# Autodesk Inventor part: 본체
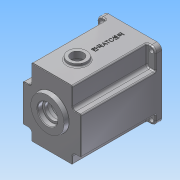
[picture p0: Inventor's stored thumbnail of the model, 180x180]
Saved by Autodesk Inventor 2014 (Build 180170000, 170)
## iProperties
Created: 2016-02
Part Number: 본체
Material: 알루미늄 6061
Document SubType Name: Modeling
Designer: mduedu
Density: 2.71 g/cm^3
Appearance: 알루미늄 - 평지
Mass: 1343.57 g
Surface Area: 1127.09 cm^2
Volume: 495.782 cm^3
Author: mduedu
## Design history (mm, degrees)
sketch "스케치1"
  geometry: L1 (-47, -47)-(47, -47); L2 (47, -47)-(47, 63); L3 (47, 63)-(-47, 63); L4 (-47, 63)-(-47, -47); 2 further points
  constraints: 8 end point, 2 parallel, 1 horizontal, 1 midpoint, 1 perpendicular, 1 vertical alignment
  dimensions: "d0" = 94 distance of L2.end L3.end; "d155" = 110 distance of L1.end L2.end; "d156" = 47 distance from line of L1 point (0, 0)
extrude "돌출1" new body sketch "스케치1" distance "d2" = 130; taper "d3" = 0 deg
sketch "스케치3"
  geometry: C1 r 40 at (0, 0); 1 further point
  constraints: 1 centre point, 1 coincident
  dimensions: "d9" = 80 diameter of C1
extrude "돌출3" cut sketch "스케치3" distance "d11" = 121; taper "d12" = 0 deg
sketch "스케치4"
  geometry: C1 r 21 at (0, 11); 1 further point
  constraints: 1 centre point, 1 vertical alignment
  dimensions: "d13" = 21 radius of C1; "d15" = 11 distance of point (0, 0) C1.centre
extrude "돌출4" join sketch "스케치4" distance "d16" = 7; taper "d17" = 0 deg
sketch "스케치5"
  geometry: C1 r 15 at (0, -20); 1 further point
  constraints: 1 centre point, 1 vertical alignment
  dimensions: "d18" = 15 radius of C1; "d20" = 20 distance of point (0, 0) C1.centre
extrude "돌출5" join sketch "스케치5" distance "d21" = 7; taper "d22" = 0 deg
sketch "스케치6"
  geometry: C1 r 28 at (0, 11); A1 r 21 centre (0, 11) between (8.978, -7.984) and (-8.978, -7.984) reference; 1 further point
  constraints: 1 centre point, 1 coincident
  dimensions: "d23" = 56 diameter of C1
extrude "돌출6" join sketch "스케치6" distance "d25" = 7; taper "d26" = -10 deg
hole "구멍1" diameter "d29" = 35; stored, may be unused: countersink angle "d33" = 90 deg, drill point angle "d35" = 0 deg; dims "d27" = 10, "d28" = 10, "d30" = 6, "d31" = 4, "d32" = 2, "d34" = 10
hole "구멍2" diameter "d38" = 22; stored, may be unused: countersink angle "d42" = 90 deg, drill point angle "d44" = 0 deg; dims "d36" = 10, "d37" = 10, "d39" = 6, "d40" = 4, "d41" = 2, "d43" = 7
hole "구멍3" diameter "d47" = 19; stored, may be unused: countersink angle "d51" = 90 deg, drill point angle "d53" = 0 deg; dims "d45" = 10, "d46" = 10, "d48" = 6, "d49" = 4, "d50" = 2, "d52" = 1
hole "구멍4" diameter "d56" = 32; stored, may be unused: countersink angle "d60" = 90 deg, drill point angle "d62" = 0 deg; dims "d54" = 10, "d55" = 10, "d57" = 6, "d58" = 4, "d59" = 2, "d61" = 8
hole "구멍5" diameter "d65" = 25; stored, may be unused: countersink angle "d69" = 90 deg, drill point angle "d71" = 0 deg; dims "d63" = 10, "d64" = 10, "d66" = 6, "d67" = 4, "d68" = 2, "d70" = 8
fillet "모깎기2" dims "d73" = 0.3
fillet "모깎기3" dims "d74" = 2
chamfer "모따기1" distance "d75" = 1; stored, may be unused: second distance "d76" = 2, angle "d77" = 45 deg
fillet "모깎기4" dims "d78" = 3
sketch "스케치16"
  geometry: L1 (-23, 32.726)-(23, 32.726); L2 (23, 32.726)-(23, 53); L3 (23, 53)-(-23, 53); L4 (-23, 53)-(-23, 32.726); L5 (-47, 63)-(47, 63) reference; 3 further points
  constraints: 8 end point, 2 parallel, 1 horizontal, 1 midpoint, 1 perpendicular, 1 vertical alignment, 2 other
  dimensions: "d160" = 46 distance of L2.end L3.end; "d163" = 10 distance between parallel lines of L3 L5
extrude "돌출15" cut sketch "스케치16" stored distance "d164" = 10; taper "d165" = 0 deg
fillet "모깎기5" dims "d79" = 2
fillet "모깎기15" dims "d166" = 5
sketch "스케치7"
  geometry: L1 (-23, 48)-(-23, 35.228) reference; L2 (23, 35.228)-(23, 48) reference; L3 (18, 53)-(-18, 53) reference; L4 (47, 63)-(47, -47) reference; L5 (47, -47)-(-47, -47) reference; L6 (-47, -47)-(-47, 63) reference; L7 (-47, 63)-(47, 63) reference; L8 (-26, 48)-(-26, 35.228); L9 (26, 35.228)-(26, 48); L10 (18, 56)-(-18, 56); C1 r 43 at (0, 0); A1 r 5 centre (-18, 48) between (-18, 53) and (-23, 48) reference; A2 r 5 centre (-28, 35.228) between (-24.889, 31.314) and (-23, 35.228) reference; A3 r 40 centre (0, 0) between (-24.889, 31.314) and (24.889, 31.314) reference; A4 r 5 centre (28, 35.228) between (23, 35.228) and (24.889, 31.314) reference; A5 r 5 centre (18, 48) between (23, 48) and (18, 53) reference; A6 r 8 centre (-18, 48) between (-18, 56) and (-26, 48); A7 r 2 centre (-28, 35.228) between (-26.756, 33.662) and (-26, 35.228); A8 r 43 centre (0, 0) between (-26.756, 33.662) and (26.756, 33.662); A9 r 2 centre (28, 35.228) between (26, 35.228) and (26.756, 33.662); A10 r 8 centre (18, 48) between (26, 48) and (18, 56); 1 further point
  constraints: 10 point on circle, 6 centre point, 6 end point, 1 coincident, 7 other
  dimensions: "d80" = 86 diameter of C1; "d167" = 3 distance between parallel lines of L3 L10
extrude "돌출7" cut sketch "스케치7" distance "d83" = 9; taper "d84" = 0 deg
sketch "스케치8" dims "d168" = 36
  geometry: L1 (-36, 4)-(-39.799, 4); L2 (-36, -4)-(-39.799, -4); A1 r 4 centre (-36, 0) between (-36, 4) and (-36, -4); A2 r 40 centre (0, 0) between (-24.889, 31.314) and (24.889, 31.314) reference; A3 r 40 centre (0, 0) between (-39.799, 4) and (-39.799, -4); 2 further points
  constraints: 5 point on circle, 4 end point, 2 centre point, 2 coincident, 2 horizontal alignment, 2 tangent, 1 horizontal, 1 parallel, 2 other
  dimensions: "d169" = 4 radius of A1
extrude "돌출9" join sketch "스케치8" stored distance "d89" = 9; taper "d90" = 0 deg
fillet "모깎기6" dims "d91" = 3.5
sketch "스케치9"
  geometry: L1 (47, 63)-(-47, 63) reference; L2 (47, -47)-(47, 63) reference; L3 (47, 63)-(33, 63); L4 (33, 63)-(33, 30); L5 (33, 30)-(47, 30); L6 (47, 30)-(47, 63); 2 further points
  constraints: 8 end point, 2 parallel, 1 horizontal, 1 perpendicular
  dimensions: "d95" = 33 distance from line of L4 point (0, 0); "d96" = 30 distance from line of L5 point (0, 0)
extrude "돌출10" cut sketch "스케치9" distance "d97" = 120; taper "d98" = 0 deg
sketch "스케치11"
  geometry: L1 (-40, -40)-(40, -40); L2 (40, -40)-(40, 56); L3 (40, 56)-(-40, 56); L4 (-40, 56)-(-40, -40); L5 (-47, -47)-(47, -47) reference; L6 (47, 63)-(-47, 63) reference; L7 (-47, 63)-(-47, -47) reference; C1 r 3.5 at (-40, 56); C2 r 3.5 at (40, 56); C3 r 3.5 at (40, -40); C4 r 3.5 at (-40, -40); 1 further point
  constraints: 8 end point, 4 centre point, 4 coincident, 3 equal radius, 2 parallel, 1 horizontal, 1 perpendicular
  dimensions: "d109" = 80 distance of L2.end L3.end; "d112" = 7 diameter of C1; "d157" = 7 distance from line of L1.start L5; "d158" = 7 distance between parallel lines of L6 L3; "d159" = 7 distance from line of L7 L3.end
extrude "돌출12" cut sketch "스케치11" stored distance "d113" = 63; taper "d114" = 0 deg
fillet "모깎기7" dims "d115" = 8
fillet "모깎기8" dims "d116" = 5
fillet "모깎기11" dims "d119" = 2
fillet "모깎기12" dims "d120" = 2
fillet "모깎기13" dims "d121" = 2
sketch "스케치12"
  geometry: 3 further points
  constraints: 2 horizontal alignment
hole "구멍6" sketch "스케치12" at (36, 0), (-36, 0) diameter "d122" = 3.242; stored, may be unused: countersink angle "d126" = 90 deg, drill point angle "d128" = 120 deg; dims "d123" = 7, "d124" = 4, "d125" = 2, "d127" = 9
sketch "스케치13"
  geometry: L1 (-33, 35)-(-33, 61) reference; L2 (-31, 63)-(31, 63) reference; L3 (33, 61)-(33, 35) reference; L4 (33, -35)-(33, -45) reference; L5 (31, -47)-(-31, -47) reference; L6 (-33, -45)-(-33, -35) reference; L7 (38, 30)-(45, 30) reference; L8 (47, 28)-(47, -28) reference; L9 (45, -30)-(38, -30) reference; L10 (-38, -30)-(-45, -30) reference; L11 (-47, -28)-(-47, 28) reference; L12 (-45, 30)-(-38, 30) reference; L13 (31, 62)-(-31, 62); L14 (-32, 61)-(-32, 35); L15 (-38, 29)-(-45, 29); L16 (-46, 28)-(-46, -28); L17 (-45, -29)-(-38, -29); L18 (-32, -35)-(-32, -45); L19 (-31, -46)-(31, -46); L20 (32, -45)-(32, -35); L21 (38, -29)-(45, -29); L22 (46, -28)-(46, 28); L23 (45, 29)-(38, 29); L24 (32, 35)-(32, 61); L25 (38, 30)-(45, 30) reference; L26 (47, 28)-(47, -28) reference; L27 (45, -30)-(38, -30) reference; L28 (33, -35)-(33, -45) reference; L29 (31, -47)-(-31, -47) reference; L30 (-33, -45)-(-33, -35) reference; L31 (-38, -30)-(-45, -30) reference; L32 (-47, -28)-(-47, 28) reference; L33 (-45, 30)-(-38, 30) reference; L34 (-33, 35)-(-33, 61) reference; L35 (33, 61)-(33, 35) reference; L36 (-31, 63)-(31, 63) reference; C1 r 16 at (0, 11) reference; C2 r 28 at (0, 11) reference; C3 r 16 at (0, 11) reference; C4 r 28 at (0, 11) reference; A1 r 5 centre (-38, 35) between (-38, 30) and (-33, 35) reference; A2 r 2 centre (-31, 61) between (-31, 63) and (-33, 61) reference; A3 r 2 centre (31, 61) between (33, 61) and (31, 63) reference; A4 r 5 centre (38, 35) between (33, 35) and (38, 30) reference; A5 r 5 centre (38, -35) between (38, -30) and (33, -35) reference; A6 r 2 centre (31, -45) between (31, -47) and (33, -45) reference; A7 r 2 centre (-31, -45) between (-33, -45) and (-31, -47) reference; A8 r 5 centre (-38, -35) between (-33, -35) and (-38, -30) reference; A9 r 2 centre (45, 28) between (47, 28) and (45, 30) reference; A10 r 2 centre (45, -28) between (45, -30) and (47, -28) reference; A11 r 2 centre (-45, -28) between (-47, -28) and (-45, -30) reference; A12 r 2 centre (-45, 28) between (-45, 30) and (-47, 28) reference; A13 r 1 centre (-31, 61) between (-31, 62) and (-32, 61); A14 r 6 centre (-38, 35) between (-38, 29) and (-32, 35); A15 r 1 centre (-45, 28) between (-45, 29) and (-46, 28); A16 r 1 centre (-45, -28) between (-46, -28) and (-45, -29); A17 r 6 centre (-38, -35) between (-32, -35) and (-38, -29); A18 r 1 centre (-31, -45) between (-32, -45) and (-31, -46); A19 r 1 centre (31, -45) between (31, -46) and (32, -45); A20 r 6 centre (38, -35) between (38, -29) and (32, -35); A21 r 1 centre (45, -28) between (45, -29) and (46, -28); A22 r 1 centre (45, 28) between (46, 28) and (45, 29); A23 r 6 centre (38, 35) between (32, 35) and (38, 29); A24 r 1 centre (31, 61) between (32, 61) and (31, 62); A25 r 5 centre (38, 35) between (33, 35) and (38, 30) reference; A26 r 2 centre (45, 28) between (47, 28) and (45, 30) reference; A27 r 2 centre (45, -28) between (45, -30) and (47, -28) reference; A28 r 5 centre (38, -35) between (38, -30) and (33, -35) reference; A29 r 2 centre (31, -45) between (31, -47) and (33, -45) reference; A30 r 2 centre (-31, -45) between (-33, -45) and (-31, -47) reference; A31 r 5 centre (-38, -35) between (-33, -35) and (-38, -30) reference; A32 r 2 centre (-45, -28) between (-47, -28) and (-45, -30) reference; A33 r 2 centre (-45, 28) between (-45, 30) and (-47, 28) reference; A34 r 5 centre (-38, 35) between (-38, 30) and (-33, 35) reference; A35 r 2 centre (-31, 61) between (-31, 63) and (-33, 61) reference; A36 r 2 centre (31, 61) between (33, 61) and (31, 63) reference
  constraints: 24 end point, 24 point on circle, 12 centre point, 23 other
  dimensions: "d154" = 1 distance between parallel lines of L13 L2
extrude "돌출13" cut sketch "스케치13" distance "d130" = 1; taper "d131" = 0 deg
fillet "모깎기14" dims "d147" = 0.3
sketch "스케치15"
  geometry: L1 (78, 0)-(0, 0) reference; 3 further points
  constraints: 1 midpoint, 1 vertical alignment, 1 other
  dimensions: "d148" = 40 distance of point (39, -40) point (39, 0)
feature "엠보싱1" sketch "스케치15" dims "d22" = 0, "d149" = 0.5, "d150" = 0
chamfer "모따기4" distance "d151" = 1; stored, may be unused: second distance "d152" = 2, angle "d153" = 45 deg
sketch "스케치17"
  geometry: L1 (39.004, -17.213)-(39.004, -18.809) reference; L2 (39.004, -18.809)-(38.548, -18.809) reference; L3 (38.548, -18.809)-(38.548, -17.213) reference; L4 (38.548, -17.213)-(35.455, -17.213) reference; L5 (35.455, -17.213)-(35.455, -16.822) reference; L6 (35.772, -16.659)-(42.578, -16.659) reference; L7 (42.578, -16.659)-(42.578, -17.213) reference; L8 (42.578, -17.213)-(39.004, -17.213) reference; L9 (38.223, -56.73)-(38.695, -56.73) reference; L10 (38.695, -56.73)-(38.695, -58.073) reference; L11 (38.695, -58.073)-(40.787, -58.073) reference; L12 (40.787, -58.073)-(40.787, -58.643) reference; L13 (40.787, -58.643)-(35.398, -58.643) reference; L14 (35.398, -58.643)-(35.398, -58.277) reference; L15 (35.715, -58.073)-(38.223, -58.073) reference; L16 (38.223, -58.073)-(38.223, -56.73) reference; L17 (41.927, -57.813)-(42.383, -57.813) reference; L18 (42.383, -57.813)-(42.383, -63.031) reference; L19 (42.383, -63.031)-(40.429, -63.031) reference; L20 (40.429, -63.031)-(40.429, -62.608) reference; L21 (40.689, -62.478)-(41.927, -62.478) reference; L22 (41.927, -62.478)-(41.927, -57.813) reference; L23 (36.09, -60.849)-(36.09, -62.624) reference; L24 (36.09, -62.624)-(35.666, -62.624) reference; L25 (35.666, -62.624)-(35.666, -60.849) reference; L26 (35.666, -60.849)-(36.09, -60.849) reference; L27 (37.058, -64.057)-(36.635, -64.057) reference; L28 (36.635, -64.057)-(36.635, -59.539) reference; L29 (36.635, -59.539)-(37.058, -59.539) reference; L30 (37.058, -59.539)-(37.058, -64.057) reference; L31 (42.138, -43.501)-(40.307, -44.168) reference; L32 (40.307, -44.168)-(40.307, -46.871) reference; L33 (40.307, -46.871)-(42.138, -47.555) reference; L34 (42.138, -47.555)-(42.138, -48.133) reference; L35 (42.138, -48.133)-(36.138, -45.853) reference; L36 (36.138, -45.853)-(36.138, -45.202) reference; L37 (36.138, -45.202)-(42.138, -42.923) reference; L38 (42.138, -42.923)-(42.138, -43.501) reference; L39 (36.725, -45.536)-(39.81, -46.684) reference; L40 (39.81, -46.684)-(39.81, -44.364) reference; L41 (39.81, -44.364)-(36.725, -45.536) reference; L42 (40.022, -52.114)-(40.022, -49.94) reference; L43 (40.022, -49.94)-(42.57, -49.94) reference; L44 (42.57, -49.94)-(42.57, -50.494) reference; L45 (42.57, -50.494)-(40.469, -50.494) reference; L46 (40.469, -50.494)-(40.469, -55.094) reference; L47 (40.469, -55.094)-(40.022, -55.094) reference; L48 (40.022, -55.094)-(40.022, -52.659) reference; L49 (40.022, -52.659)-(38.556, -52.659) reference; L50 (38.556, -52.659)-(38.556, -55.973) reference; L51 (38.556, -55.973)-(38.109, -55.973) reference; L52 (38.109, -55.973)-(38.109, -50.73) reference; L53 (36.106, -50.388)-(36.106, -54.955) reference; L54 (36.106, -54.955)-(35.65, -54.955) reference; L55 (35.65, -54.955)-(35.65, -49.81) reference; L56 (38.109, -50.136)-(38.109, -48.768) reference; L57 (38.109, -48.768)-(38.556, -48.768) reference; L58 (38.556, -48.768)-(38.556, -52.114) reference; L59 (38.556, -52.114)-(40.022, -52.114) reference; L60 (36.138, -38.168)-(36.635, -38.168) reference; L61 (36.635, -38.168)-(36.635, -40.041) reference; L62 (36.635, -40.041)-(42.138, -40.041) reference; L63 (42.138, -40.041)-(42.138, -40.586) reference; L64 (42.138, -40.586)-(36.635, -40.586) reference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; C1 r 10 at (39, -89); A1 r 4 centre (4, -12) between (8, -12) and (4, -8) reference; A2 r 4 centre (74, -12) between (74, -8) and (70, -12) reference; 61 further points
  constraints: 2 end point, 1 centre point, 1 midpoint, 1 point on line, 76 other
  dimensions: "d170" = 20 diameter of C1; "d171" = 41 distance from line of C1.centre L110
extrude "돌출16" cut sketch "스케치17" stored distance "d172" = 10; taper "d173" = 0 deg
sketch "스케치18"
  geometry: C1 r 10 at (39, -89) reference; C2 r 15 at (39, -89); 1 further point
  constraints: 1 centre point, 1 coincident
  dimensions: "d174" = 30 diameter of C2
extrude "돌출17" join sketch "스케치18" distance "d175" = 5; taper "d176" = 0 deg
fillet "모깎기16" dims "d177" = 2
sketch "스케치19"
  geometry: C1 r 10 at (18, 80) reference; C2 r 15 at (18, 80); 1 further point
  constraints: 1 centre point, 1 coincident
  dimensions: "d178" = 30 diameter of C2
extrude "돌출18" cut sketch "스케치19" distance "d181" = 5; taper "d182" = 0 deg
chamfer "모따기5" distance "d183" = 0.5; stored, may be unused: second distance "d184" = 2, angle "d185" = 45 deg
node "솔리드1"
pattern_circular "원형 패턴1" dims angle "d93" = 360 deg
mirror "대칭1"
mirror "대칭2"
node "절단 모서리 투영1"
node "절단 모서리 투영2"
node "절단 모서리 투영3"
node "절단 모서리 투영4"
